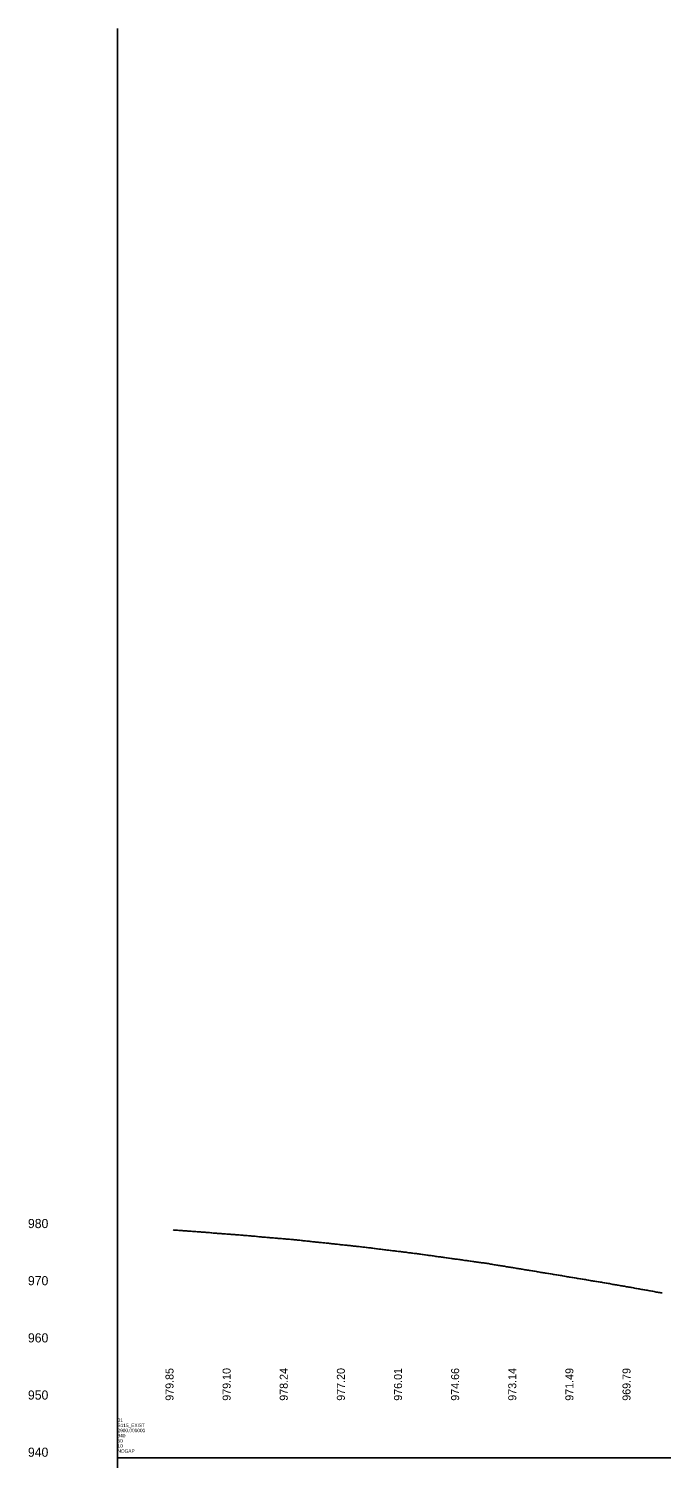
# Model space of a CAD drawing. Extents: x 1619269 to 1623088, y 1189107 to 1192385.
# Drawn here: x 1621498 to 1622052, y 1190356 to 1191607 of the extents above; entities that cross this region are included whole.
import ezdxf

# ---------------------------------------------------------------- set-up
doc = ezdxf.new("R2010")
doc.units = 0
for name, color, linetype in [('RD_DDB_ElevTX', 7, 'Continuous'), ('RD_DDB_Profile_EX', 7, 'Continuous'), ('RD_DDB_StripGrade', 7, 'Continuous'), ('RD_GPK_Profile_Cell', 7, 'Continuous')]:
    doc.layers.add(name, color=color, linetype=linetype)

msp = doc.modelspace()

# ---------------------------------------------------------------- linework, layer by layer
at = {"layer": 'RD_DDB_Profile_EX'}
for points in [[(1621624.8, 1190556), (1621625.8, 1190555.9), (1621626.8, 1190555.8), (1621627.8, 1190555.8), (1621628.8, 1190555.7), (1621629.8, 1190555.6), (1621630.8, 1190555.5), (1621631.8, 1190555.5), (1621632.8, 1190555.4), (1621633.8, 1190555.3), (1621634.8, 1190555.2), (1621635.8, 1190555.2), (1621636.8, 1190555.1), (1621637.8, 1190555), (1621638.8, 1190554.9), (1621639.8, 1190554.9), (1621640.8, 1190554.8), (1621641.8, 1190554.7), (1621642.8, 1190554.6), (1621643.8, 1190554.6), (1621644.8, 1190554.5), (1621645.8, 1190554.4), (1621646.8, 1190554.3), (1621647.8, 1190554.2), (1621648.8, 1190554.2), (1621649.8, 1190554.1), (1621650.8, 1190554), (1621651.8, 1190553.9), (1621652.8, 1190553.9), (1621653.8, 1190553.8), (1621654.8, 1190553.7), (1621655.8, 1190553.6), (1621656.8, 1190553.6), (1621657.8, 1190553.5), (1621658.8, 1190553.4), (1621659.8, 1190553.3), (1621660.8, 1190553.3), (1621661.8, 1190553.2), (1621662.8, 1190553.1), (1621663.8, 1190553), (1621664.8, 1190553), (1621665.8, 1190552.9), (1621666.8, 1190552.8), (1621667.8, 1190552.7), (1621668.8, 1190552.7), (1621669.8, 1190552.6), (1621670.8, 1190552.5), (1621671.8, 1190552.4), (1621672.8, 1190552.3), (1621673.8, 1190552.3), (1621674.8, 1190552.2), (1621675.8, 1190552.1), (1621676.8, 1190552), (1621677.8, 1190552), (1621678.8, 1190551.9), (1621679.8, 1190551.8), (1621680.8, 1190551.7), (1621681.8, 1190551.6), (1621682.8, 1190551.6), (1621683.8, 1190551.5), (1621684.8, 1190551.4), (1621685.8, 1190551.3), (1621686.8, 1190551.2), (1621687.8, 1190551.1), (1621688.8, 1190551), (1621689.8, 1190551), (1621690.8, 1190550.9), (1621691.8, 1190550.8), (1621692.8, 1190550.7), (1621693.8, 1190550.6), (1621694.8, 1190550.5), (1621695.8, 1190550.4), (1621696.8, 1190550.4), (1621697.8, 1190550.3), (1621698.8, 1190550.2), (1621699.8, 1190550.1), (1621700.8, 1190550), (1621701.8, 1190549.9), (1621702.8, 1190549.8), (1621703.8, 1190549.8), (1621704.8, 1190549.7), (1621705.8, 1190549.6), (1621706.8, 1190549.5), (1621707.8, 1190549.4), (1621708.8, 1190549.3), (1621709.8, 1190549.2), (1621710.8, 1190549.1), (1621711.8, 1190549.1), (1621712.8, 1190549), (1621713.8, 1190548.9), (1621714.8, 1190548.8), (1621715.8, 1190548.7), (1621716.8, 1190548.6), (1621717.8, 1190548.5), (1621718.8, 1190548.5), (1621719.8, 1190548.4), (1621720.8, 1190548.3), (1621721.8, 1190548.2), (1621722.8, 1190548.1), (1621723.8, 1190548), (1621724.8, 1190547.9)], [(1621724.8, 1190547.9), (1621725.8, 1190547.9), (1621726.8, 1190547.8), (1621727.8, 1190547.7), (1621728.8, 1190547.6), (1621729.8, 1190547.5), (1621730.8, 1190547.4), (1621731.8, 1190547.3), (1621732.8, 1190547.2), (1621733.8, 1190547.1), (1621734.8, 1190547), (1621735.8, 1190546.9), (1621736.8, 1190546.8), (1621737.8, 1190546.7), (1621738.8, 1190546.6), (1621739.8, 1190546.5), (1621740.8, 1190546.4), (1621741.8, 1190546.3), (1621742.8, 1190546.2), (1621743.8, 1190546.1), (1621744.8, 1190546), (1621745.8, 1190545.9), (1621746.8, 1190545.7), (1621747.8, 1190545.6), (1621748.8, 1190545.5), (1621749.8, 1190545.4), (1621750.8, 1190545.3), (1621751.8, 1190545.2), (1621752.8, 1190545.1), (1621753.8, 1190545), (1621754.8, 1190544.9), (1621755.8, 1190544.8), (1621756.8, 1190544.7), (1621757.8, 1190544.6), (1621758.8, 1190544.5), (1621759.8, 1190544.4), (1621760.8, 1190544.3), (1621761.8, 1190544.2), (1621762.8, 1190544.1), (1621763.8, 1190543.9), (1621764.8, 1190543.8), (1621765.8, 1190543.7), (1621766.8, 1190543.6), (1621767.8, 1190543.5), (1621768.8, 1190543.4), (1621769.8, 1190543.3), (1621770.8, 1190543.2), (1621771.8, 1190543.1), (1621772.8, 1190543), (1621773.8, 1190542.9), (1621774.8, 1190542.8), (1621775.8, 1190542.7), (1621776.8, 1190542.6), (1621777.8, 1190542.5), (1621778.8, 1190542.4), (1621779.8, 1190542.3), (1621780.8, 1190542.1), (1621781.8, 1190542), (1621782.8, 1190541.9), (1621783.8, 1190541.8), (1621784.8, 1190541.7), (1621785.8, 1190541.6), (1621786.8, 1190541.5), (1621787.8, 1190541.4), (1621788.8, 1190541.3), (1621789.8, 1190541.1), (1621790.8, 1190541), (1621791.8, 1190540.9), (1621792.8, 1190540.8), (1621793.8, 1190540.7), (1621794.8, 1190540.5), (1621795.8, 1190540.4), (1621796.8, 1190540.3), (1621797.8, 1190540.2), (1621798.8, 1190540), (1621799.8, 1190539.9), (1621800.8, 1190539.8), (1621801.8, 1190539.7), (1621802.8, 1190539.6), (1621803.8, 1190539.4), (1621804.8, 1190539.3), (1621805.8, 1190539.2), (1621806.8, 1190539.1), (1621807.8, 1190538.9), (1621808.8, 1190538.8), (1621809.8, 1190538.7), (1621810.8, 1190538.6), (1621811.8, 1190538.4), (1621812.8, 1190538.3), (1621813.8, 1190538.2), (1621814.8, 1190538.1), (1621815.8, 1190538), (1621816.8, 1190537.8), (1621817.8, 1190537.7), (1621818.8, 1190537.6), (1621819.8, 1190537.5), (1621820.8, 1190537.3), (1621821.8, 1190537.2), (1621822.8, 1190537.1), (1621823.8, 1190537), (1621824.8, 1190536.9)], [(1621824.8, 1190536.9), (1621825.8, 1190536.7), (1621826.8, 1190536.6), (1621827.8, 1190536.5), (1621828.8, 1190536.4), (1621829.8, 1190536.2), (1621830.8, 1190536.1), (1621831.8, 1190536), (1621832.8, 1190535.9), (1621833.8, 1190535.7), (1621834.8, 1190535.6), (1621835.8, 1190535.5), (1621836.8, 1190535.4), (1621837.8, 1190535.3), (1621838.8, 1190535.1), (1621839.8, 1190535), (1621840.8, 1190534.9), (1621841.8, 1190534.7), (1621842.8, 1190534.6), (1621843.8, 1190534.4), (1621844.8, 1190534.3), (1621845.8, 1190534.2), (1621846.8, 1190534), (1621847.8, 1190533.9), (1621848.8, 1190533.7), (1621849.8, 1190533.6), (1621850.8, 1190533.5), (1621851.8, 1190533.3), (1621852.8, 1190533.2), (1621853.8, 1190533), (1621854.8, 1190532.9), (1621855.8, 1190532.8), (1621856.8, 1190532.6), (1621857.8, 1190532.5), (1621858.8, 1190532.4), (1621859.8, 1190532.2), (1621860.8, 1190532.1), (1621861.8, 1190531.9), (1621862.8, 1190531.8), (1621863.8, 1190531.7), (1621864.8, 1190531.5), (1621865.8, 1190531.4), (1621866.8, 1190531.2), (1621867.8, 1190531.1), (1621868.8, 1190531), (1621869.8, 1190530.8), (1621870.8, 1190530.7), (1621871.8, 1190530.5), (1621872.8, 1190530.4), (1621873.8, 1190530.3), (1621874.8, 1190530.1), (1621875.8, 1190530), (1621876.8, 1190529.8), (1621877.8, 1190529.7), (1621878.8, 1190529.6), (1621879.8, 1190529.4), (1621880.8, 1190529.3), (1621881.8, 1190529.2), (1621882.8, 1190529), (1621883.8, 1190528.9), (1621884.8, 1190528.7), (1621885.8, 1190528.6), (1621886.8, 1190528.5), (1621887.8, 1190528.3), (1621888.8, 1190528.2), (1621889.8, 1190528), (1621890.8, 1190527.9), (1621891.8, 1190527.8), (1621892.8, 1190527.6), (1621893.8, 1190527.5), (1621894.8, 1190527.3), (1621895.8, 1190527.2), (1621896.8, 1190527.1), (1621897.8, 1190526.9), (1621898.8, 1190526.8), (1621899.8, 1190526.6), (1621900.8, 1190526.5), (1621901.8, 1190526.3), (1621902.8, 1190526.1), (1621903.8, 1190526), (1621904.8, 1190525.8), (1621905.8, 1190525.6), (1621906.8, 1190525.5), (1621907.8, 1190525.3), (1621908.8, 1190525.2), (1621909.8, 1190525), (1621910.8, 1190524.8), (1621911.8, 1190524.7), (1621912.8, 1190524.5), (1621913.8, 1190524.3), (1621914.8, 1190524.2), (1621915.8, 1190524), (1621916.8, 1190523.8), (1621917.8, 1190523.7), (1621918.8, 1190523.5), (1621919.8, 1190523.4), (1621920.8, 1190523.2), (1621921.8, 1190523), (1621922.8, 1190522.9), (1621923.8, 1190522.7), (1621924.8, 1190522.5)], [(1621924.8, 1190522.5), (1621925.8, 1190522.4), (1621926.8, 1190522.2), (1621927.8, 1190522), (1621928.8, 1190521.9), (1621929.8, 1190521.7), (1621930.8, 1190521.6), (1621931.8, 1190521.4), (1621932.8, 1190521.2), (1621933.8, 1190521.1), (1621934.8, 1190520.9), (1621935.8, 1190520.7), (1621936.8, 1190520.6), (1621937.8, 1190520.4), (1621938.8, 1190520.3), (1621939.8, 1190520.1), (1621940.8, 1190519.9), (1621941.8, 1190519.8), (1621942.8, 1190519.6), (1621943.8, 1190519.4), (1621944.8, 1190519.3), (1621945.8, 1190519.1), (1621946.8, 1190518.9), (1621947.8, 1190518.8), (1621948.8, 1190518.6), (1621949.8, 1190518.5), (1621950.8, 1190518.3), (1621951.8, 1190518.1), (1621952.8, 1190518), (1621953.8, 1190517.8), (1621954.8, 1190517.6), (1621955.8, 1190517.5), (1621956.8, 1190517.3), (1621957.8, 1190517.1), (1621958.8, 1190517), (1621959.8, 1190516.8), (1621960.8, 1190516.6), (1621961.8, 1190516.5), (1621962.8, 1190516.3), (1621963.8, 1190516.1), (1621964.8, 1190516), (1621965.8, 1190515.8), (1621966.8, 1190515.6), (1621967.8, 1190515.5), (1621968.8, 1190515.3), (1621969.8, 1190515.1), (1621970.8, 1190515), (1621971.8, 1190514.8), (1621972.8, 1190514.6), (1621973.8, 1190514.5), (1621974.8, 1190514.3), (1621975.8, 1190514.1), (1621976.8, 1190514), (1621977.8, 1190513.8), (1621978.8, 1190513.6), (1621979.8, 1190513.5), (1621980.8, 1190513.3), (1621981.8, 1190513.1), (1621982.8, 1190513), (1621983.8, 1190512.8), (1621984.8, 1190512.6), (1621985.8, 1190512.5), (1621986.8, 1190512.3), (1621987.8, 1190512.1), (1621988.8, 1190512), (1621989.8, 1190511.8), (1621990.8, 1190511.6), (1621991.8, 1190511.5), (1621992.8, 1190511.3), (1621993.8, 1190511.2), (1621994.8, 1190511), (1621995.8, 1190510.8), (1621996.8, 1190510.7), (1621997.8, 1190510.5), (1621998.8, 1190510.3), (1621999.8, 1190510.2), (1622000.8, 1190510), (1622001.8, 1190509.8), (1622002.8, 1190509.7), (1622003.8, 1190509.5), (1622004.8, 1190509.3), (1622005.8, 1190509.1), (1622006.8, 1190509), (1622007.8, 1190508.8), (1622008.8, 1190508.6), (1622009.8, 1190508.4), (1622010.8, 1190508.3), (1622011.8, 1190508.1), (1622012.8, 1190507.9), (1622013.8, 1190507.7), (1622014.8, 1190507.6), (1622015.8, 1190507.4), (1622016.8, 1190507.2), (1622017.8, 1190507), (1622018.8, 1190506.9), (1622019.8, 1190506.7), (1622020.8, 1190506.5), (1622021.8, 1190506.3), (1622022.8, 1190506.2), (1622023.8, 1190506), (1622024.8, 1190505.8)], [(1622024.8, 1190505.8), (1622025.8, 1190505.6), (1622026.8, 1190505.5), (1622027.8, 1190505.3), (1622028.8, 1190505.1), (1622029.8, 1190504.9), (1622030.8, 1190504.7), (1622031.8, 1190504.6), (1622032.8, 1190504.4), (1622033.8, 1190504.2), (1622034.8, 1190504), (1622035.8, 1190503.9), (1622036.8, 1190503.7), (1622037.8, 1190503.5), (1622038.8, 1190503.3), (1622039.8, 1190503.2), (1622040.8, 1190503), (1622041.8, 1190502.8), (1622042.8, 1190502.6), (1622043.8, 1190502.5), (1622044.8, 1190502.3), (1622045.8, 1190502.1), (1622046.8, 1190501.9), (1622047.8, 1190501.7), (1622048.8, 1190501.6), (1622049.8, 1190501.4), (1622050.8, 1190501.2), (1622051.8, 1190501), (1622052.8, 1190500.9)]]:
    msp.add_lwpolyline(points, dxfattribs=at)
at = {"layer": 'RD_GPK_Profile_Cell'}
for q in [(1621576.2, 1191606.6), (1623076.2, 1190356.6), (1621576.2, 1189106.6)]:
    msp.add_line((1621576.2, 1190356.6), q, dxfattribs=at)

# ---------------------------------------------------------------- texts
at = {"layer": 'RD_DDB_ElevTX'}
for s, p in [('980', (1621497.8, 1190557.6)), ('970', (1621497.8, 1190507.6)), ('960', (1621497.8, 1190457.6)), ('950', (1621497.8, 1190407.6)), ('940', (1621497.8, 1190357.6))]:
    msp.add_text(s, height=8, dxfattribs=at).set_placement(p)
at = {"layer": 'RD_DDB_StripGrade'}
for s, p in [('979.85', (1621625.2, 1190406.6)), ('979.10', (1621675.2, 1190406.6)), ('978.24', (1621725.2, 1190406.6)), ('977.20', (1621775.2, 1190406.6)), ('976.01', (1621825.2, 1190406.6)), ('974.66', (1621875.2, 1190406.6)), ('973.14', (1621925.2, 1190406.6)), ('971.49', (1621975.2, 1190406.6)), ('969.79', (1622025.2, 1190406.6))]:
    msp.add_text(s, height=7, rotation=90, dxfattribs=at).set_placement(p)
at = {"layer": 'RD_GPK_Profile_Cell'}
for s, p in [('01', (1621576.2, 1190388.1)), ('S115_EXIST', (1621576.2, 1190383.6)), ('2900.000000', (1621576.2, 1190379.1)), ('50', (1621576.2, 1190370.1)), ('940', (1621576.2, 1190374.6)), ('10', (1621576.2, 1190365.6)), ('NOGAP', (1621576.2, 1190361.1))]:
    msp.add_text(s, height=3, dxfattribs=at).set_placement(p)

doc.saveas('drawing.dxf')
